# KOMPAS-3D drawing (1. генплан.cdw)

Views: Вид 1
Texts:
  ДП.11.213.01.000.00.Д1
  СПК колхоз "Дзержинского" Даниловского МР Ярославской обл.
  Навозохранилище
  Трансформаторная подстанция
  Котельная
  Административное здание
  Медпункт
  Молочный блок
  Коровник
  Телятник для телят до 6 месяцев
  Телятник для телят 6...12 месяцев
  Помещение для нетелей
  Телятник для бычков старше 1 года
  Карантин
  Родильное отделение
  № поз.
  Хранилище для сена
  Хранилище для соломы
  Силосная башня
  Хранилище для корнеклубнеплодов
  Хранилище для конц. кормов
  Сенажная башня
  Хранилище для комб. кормов
  Водонапорная башня
  Стоянка для с/х техники
  Автогараж
  Центральная ремонтная мастерская
  ЭКСПЛИКАЦИЯ ЗДАНИЙ И СООРУЖЕНИЙ:
  Кормоцех
  УСЛОВНЫЕ ОБОЗНАЧЕНИЯ:
  - основные здания и сооружения
  - выгульные площадки
  - пожарный резервуар
  - главный въезд на территорию хозяйства
  - деревья хвойные
  - кустарник
  - трава
  - ограда
  - питательный пункт наружного освещения
  - линия наружного освещения
  - дороги
  ВЛ 10/0,4
  ДОРОГИ
  Стили документа
  Куракин
  ФГОУ ВПО ЯГСХА
  СПК колхоз "Дзержинского"
  Даниловского МР Ярославской обл.
  Шмигель
  Генплан
  ДП08Ф040200009Э0-
  Королёва
  Орлов
Dimensions and other numbers on the sheet: 25; 8; 7; 6; 4; 5; 1; 2; 3; 13; 14; 15; 16; 17; 18; 19; 20; 21; 22; 23; 24; 9; 10; 11; 12; 1:1000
